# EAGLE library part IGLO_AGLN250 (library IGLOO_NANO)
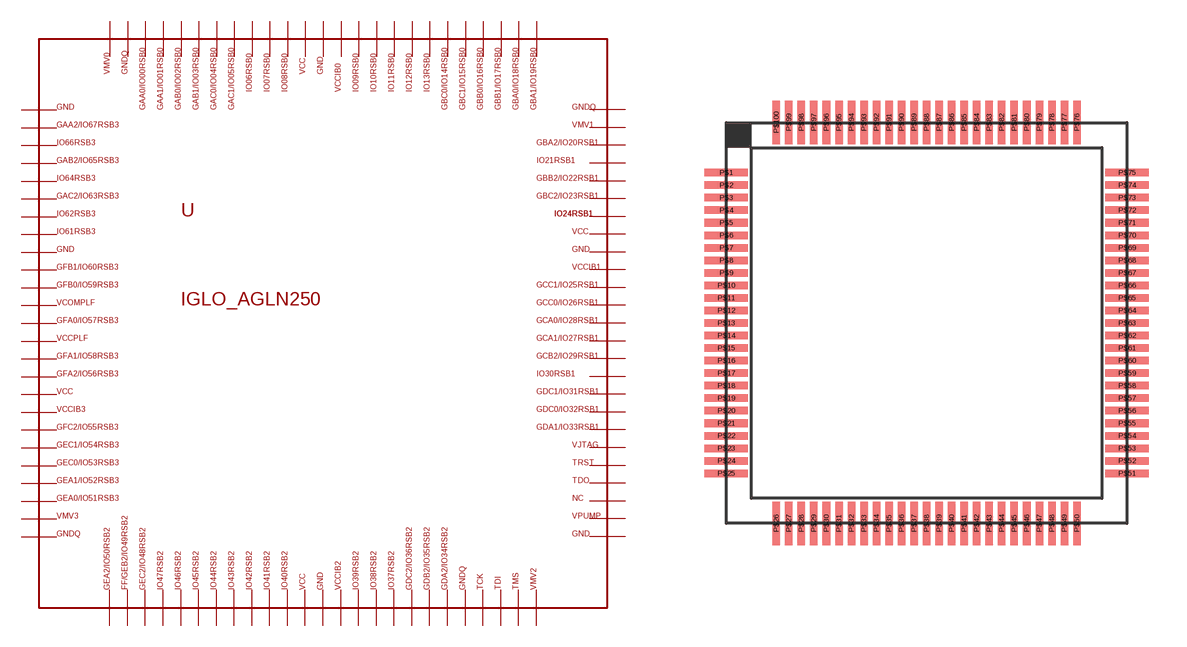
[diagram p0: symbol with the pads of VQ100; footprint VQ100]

Designator prefix -

## IGLO_AGLN250  [VQ100]
P$1  P$1  pas
P$2  P$2  pas
P$3  P$3  pas
P$4  P$4  pas
P$5  P$5  pas
P$6  P$6  pas
P$7  P$7  pas
P$8  P$8  pas
P$9  P$9  pas
P$10  P$10  pas
P$11  P$11  pas
P$12  P$12  pas
P$13  P$13  pas
P$14  P$14  pas
P$15  P$15  pas
P$16  P$16  pas
P$17  P$17  pas
P$18  P$18  pas
P$19  P$19  pas
P$20  P$20  pas
P$21  P$21  pas
P$22  P$22  pas
P$23  P$23  pas
P$24  P$24  pas
P$25  P$25  pas
P$26  P$26  pas
P$27  P$27  pas
P$28  P$28  pas
P$29  P$29  pas
P$30  P$30  pas
P$31  P$31  pas
P$32  P$32  pas
P$33  P$33  pas
P$34  P$34  pas
P$35  P$35  pas
P$36  P$36  pas
P$37  P$37  pas
P$38  P$38  pas
P$39  P$39  pas
P$40  P$40  pas
P$41  P$41  pas
P$42  P$42  pas
P$43  P$43  pas
P$44  P$44  pas
P$45  P$45  pas
P$46  P$46  pas
P$47  P$47  pas
P$48  P$48  pas
P$49  P$49  pas
P$50  P$50  pas
P$51  P$51  pas
P$52  P$52  pas
P$53  P$53  pas
P$54  P$54  pas
P$55  P$55  pas
P$56  P$56  pas
P$57  P$57  pas
P$58  P$58  pas
P$59  P$59  pas
P$60  P$60  pas
P$61  P$61  pas
P$62  P$62  pas
P$63  P$63  pas
P$64  P$64  pas
P$65  P$65  pas
P$66  P$66  pas
P$67  P$67  pas
P$68  P$68  pas
P$69  P$69  pas
P$70  P$70  pas
P$71  P$71  pas
P$72  P$72  pas
P$73  P$73  pas
P$74  P$74  pas
P$75  P$75  pas
P$76  P$76  pas
P$77  P$77  pas
P$78  P$78  pas
P$79  P$79  pas
P$80  P$80  pas
P$81  P$81  pas
P$82  P$82  pas
P$83  P$83  pas
P$84  P$84  pas
P$85  P$85  pas
P$86  P$86  pas
P$87  P$87  pas
P$88  P$88  pas
P$89  P$89  pas
P$90  P$90  pas
P$91  P$91  pas
P$92  P$92  pas
P$93  P$93  pas
P$94  P$94  pas
P$95  P$95  pas
P$96  P$96  pas
P$97  P$97  pas
P$98  P$98  pas
P$99  P$99  pas
P$100  P$100  pas

## Footprint VQ100 (pad centres in mm)
smd 1.75 x 0.3: P$1 -8,6; P$2 -8,5.5; P$3 -8,5; P$4 -8,4.5; P$5 -8,4; P$6 -8,3.5; P$7 -8,3; P$8 -8,2.5; P$9 -8,2; P$10 -8,1.5; P$11 -8,1; P$12 -8,0.5; P$13 -8,0; P$14 -8,-0.5; P$15 -8,-1; P$16 -8,-1.5; P$17 -8,-2; P$18 -8,-2.5; P$19 -8,-3; P$20 -8,-3.5; P$21 -8,-4; P$22 -8,-4.5; P$23 -8,-5; P$24 -8,-5.5; P$25 -8,-6; P$51 8,-6; P$52 8,-5.5; P$53 8,-5; P$54 8,-4.5; P$55 8,-4; P$56 8,-3.5; P$57 8,-3; P$58 8,-2.5; P$59 8,-2; P$60 8,-1.5; P$61 8,-1; P$62 8,-0.5; P$63 8,0; P$64 8,0.5; P$65 8,1; P$66 8,1.5; P$67 8,2; P$68 8,2.5; P$69 8,3; P$70 8,3.5; P$71 8,4; P$72 8,4.5; P$73 8,5; P$74 8,5.5; P$75 8,6
smd 0.3 x 1.75: P$26 -6,-8; P$27 -5.5,-8; P$28 -5,-8; P$29 -4.5,-8; P$30 -4,-8; P$31 -3.5,-8; P$32 -3,-8; P$33 -2.5,-8; P$34 -2,-8; P$35 -1.5,-8; P$36 -1,-8; P$37 -0.5,-8; P$38 0,-8; P$39 0.5,-8; P$40 1,-8; P$41 1.5,-8; P$42 2,-8; P$43 2.5,-8; P$44 3,-8; P$45 3.5,-8; P$46 4,-8; P$47 4.5,-8; P$48 5,-8; P$49 5.5,-8; P$50 6,-8; P$76 6,8; P$77 5.5,8; P$78 5,8; P$79 4.5,8; P$80 4,8; P$81 3.5,8; P$82 3,8; P$83 2.5,8; P$84 2,8; P$85 1.5,8; P$86 1,8; P$87 0.5,8; P$88 0,8; P$89 -0.5,8; P$90 -1,8; P$91 -1.5,8; P$92 -2,8; P$93 -2.5,8; P$94 -3,8; P$95 -3.5,8; P$96 -4,8; P$97 -4.5,8; P$98 -5,8; P$99 -5.5,8; P$100 -6,8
